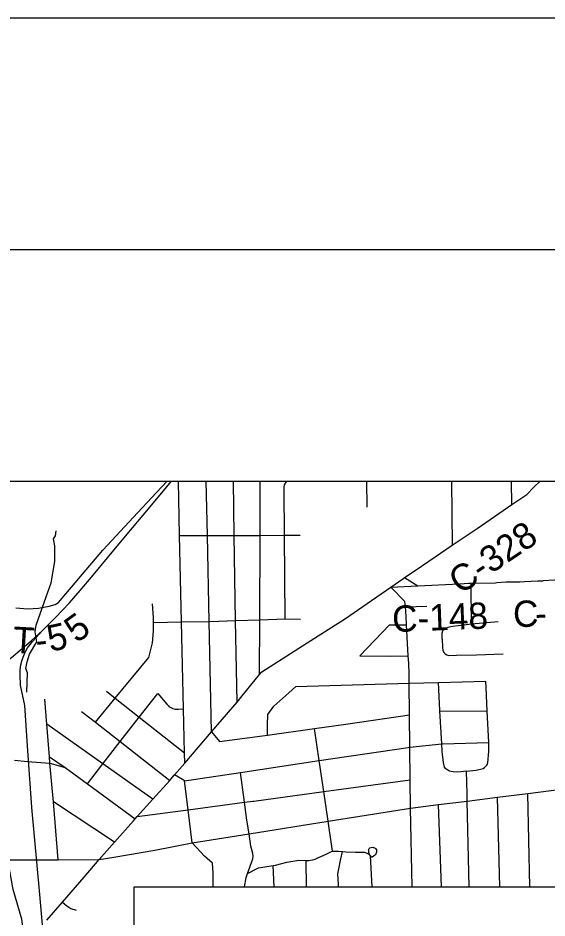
# Model space of a CAD drawing. Extents: x -37878.7 to -37844.7, y -19791.4 to -19769.4.
# Drawn here: x -37875.069 to -37873.927, y -19771.329 to -19769.385 of the extents above; entities that cross this region are included whole.
import ezdxf

# ---------------------------------------------------------------- set-up
doc = ezdxf.new("R2010")
doc.units = 0
for name, color, linetype in [('Default', 7, 'Continuous'), ('GM_X_City_Street', 7, 'Continuous'), ('GM_X_County_Road', 7, 'Continuous'), ('GM_X_County_Road_Text', 7, 'Continuous'), ('GM_X_Minor_River', 7, 'Continuous'), ('GM_X_Rail_Line', 7, 'Continuous'), ('GM_X_Township_Road', 7, 'Continuous'), ('GM_X_Township_Road_Text', 7, 'Continuous'), ('GM_X_Township_Subdivision', 7, 'Continuous'), ('SH_Border', 7, 'Continuous'), ('SH_Cut_Line', 7, 'Continuous'), ('SH_Data', 7, 'Continuous'), ('TX_P_1', 7, 'Continuous')]:
    doc.layers.add(name, color=color, linetype=linetype)

msp = doc.modelspace()

# ---------------------------------------------------------------- linework, layer by layer
at = {"layer": 'Default'}
msp.add_lwpolyline([(-37874.2328, -19770.6572), (-37874.1867, -19770.6558)], dxfattribs=at)
at = {"layer": 'GM_X_City_Street'}
for points in [[(-37874.7092, -19770.9945), (-37874.7097, -19770.9726), (-37874.7118, -19770.877), (-37874.7161, -19770.6896), (-37874.7203, -19770.5032), (-37874.7229, -19770.3854)], [(-37874.6512, -19770.9272), (-37874.6564, -19770.6884), (-37874.6603, -19770.503), (-37874.6628, -19770.3854)], [(-37874.5964, -19770.8629), (-37874.5993, -19770.6867), (-37874.6022, -19770.5028), (-37874.6041, -19770.3854)], [(-37874.5477, -19770.8032), (-37874.5473, -19770.6849), (-37874.5467, -19770.5027), (-37874.5463, -19770.3854)], [(-37874.4921, -19770.683), (-37874.4937, -19770.5025), (-37874.4946, -19770.4047), (-37874.4944, -19770.3975), (-37874.4936, -19770.3933), (-37874.4904, -19770.3875), (-37874.4891, -19770.3854)], [(-37874.3153, -19770.442), (-37874.316, -19770.3854)], [(-37874.8105, -19770.4532), (-37874.7704, -19770.4102), (-37874.7704, -19770.4102)], [(-37874.7203, -19770.5032), (-37874.6603, -19770.503), (-37874.6022, -19770.5028), (-37874.5467, -19770.5027), (-37874.4937, -19770.5025), (-37874.4603, -19770.5024)], [(-37874.1157, -19770.607), (-37874.0957, -19770.606)], [(-37874.0897, -19770.6937), (-37874.0907, -19770.6058)], [(-37874.0355, -19770.6047), (-37874.0353, -19770.6047), (-37874.0156, -19770.603), (-37874.0155, -19770.603)], [(-37874.9023, -19770.9063), (-37874.8593, -19770.8543), (-37874.7867, -19770.7665), (-37874.779, -19770.7347), (-37874.7768, -19770.7094), (-37874.7768, -19770.6909), (-37874.7768, -19770.6798), (-37874.779, -19770.6502)], [(-37874.4368, -19770.7295), (-37874.4367, -19770.7295), (-37874.362, -19770.6821), (-37874.3154, -19770.6497)], [(-37874.7768, -19770.6909), (-37874.7161, -19770.6896), (-37874.6564, -19770.6884), (-37874.636, -19770.6879), (-37874.5993, -19770.6867), (-37874.5473, -19770.6849), (-37874.4921, -19770.683), (-37874.4596, -19770.6837)], [(-37874.3311, -19770.7627), (-37874.267, -19770.6958)], [(-37874.1536, -19770.7265), (-37874.1536, -19770.7129), (-37874.1516, -19770.7086), (-37874.1502, -19770.7062), (-37874.1456, -19770.703), (-37874.14, -19770.7008), (-37874.1372, -19770.7001), (-37874.1307, -19770.6989), (-37874.1188, -19770.6972), (-37874.0897, -19770.6937), (-37874.0325, -19770.6883)], [(-37875.0071, -19771.3333), (-37874.9736, -19771.2948), (-37874.9266, -19771.2409), (-37874.8938, -19771.2024), (-37874.8608, -19771.1652), (-37874.8203, -19771.1194), (-37874.8162, -19771.1149), (-37874.812, -19771.1101), (-37874.778, -19771.0722), (-37874.7417, -19771.0318), (-37874.739, -19771.0288), (-37874.7314, -19771.02), (-37874.7092, -19770.9945), (-37874.6512, -19770.9272), (-37874.6054, -19770.874), (-37874.5964, -19770.8629), (-37874.5854, -19770.8493), (-37874.5477, -19770.8032), (-37874.5431, -19770.797), (-37874.4368, -19770.7295)], [(-37874.1536, -19770.7265), (-37874.1524, -19770.7444), (-37874.1515, -19770.7512), (-37874.149, -19770.7561), (-37874.1466, -19770.7584), (-37874.1434, -19770.7607), (-37874.1388, -19770.7618), (-37874.1225, -19770.761), (-37874.0793, -19770.7609), (-37874.0218, -19770.7588)], [(-37874.3311, -19770.7627), (-37874.2656, -19770.7637)], [(-37874.2251, -19770.7863), (-37874.2255, -19770.7784), (-37874.2255, -19770.7784)], [(-37874.2179, -19771.262), (-37874.222, -19771.0918), (-37874.2225, -19771.0309), (-37874.2232, -19770.9601), (-37874.2238, -19770.8905), (-37874.2244, -19770.822), (-37874.2246, -19770.7943)], [(-37874.5306, -19770.9339), (-37874.5307, -19770.9118), (-37874.5296, -19770.8897), (-37874.5167, -19770.8717), (-37874.4848, -19770.8424), (-37874.4694, -19770.8289), (-37874.2244, -19770.822), (-37874.161, -19770.8202), (-37874.0591, -19770.8173)], [(-37874.1006, -19771.0122), (-37874.1195, -19771.0141), (-37874.1292, -19771.0134), (-37874.1371, -19771.0117), (-37874.1409, -19771.0096), (-37874.1457, -19771.0068), (-37874.1484, -19771.003), (-37874.1502, -19770.993), (-37874.1533, -19770.9695), (-37874.1542, -19770.9529), (-37874.1582, -19770.8819), (-37874.1583, -19770.8807), (-37874.161, -19770.8202)], [(-37874.1006, -19771.0122), (-37874.0795, -19771.0099), (-37874.0648, -19771.0063), (-37874.0615, -19771.0038), (-37874.057, -19770.9986), (-37874.0553, -19770.9965), (-37874.0543, -19770.9941), (-37874.0525, -19770.9697), (-37874.0525, -19770.95), (-37874.0558, -19770.8821), (-37874.0582, -19770.831), (-37874.0591, -19770.8173)], [(-37874.9196, -19771.039), (-37874.886, -19770.9959), (-37874.8487, -19770.9481), (-37874.8074, -19770.8953), (-37874.7673, -19770.8438)], [(-37874.8782, -19770.8394), (-37874.8593, -19770.8543), (-37874.8074, -19770.8953), (-37874.7097, -19770.9726)], [(-37874.7673, -19770.8438), (-37874.7478, -19770.8673), (-37874.7446, -19770.871), (-37874.7429, -19770.8727), (-37874.7395, -19770.8746), (-37874.7349, -19770.8767), (-37874.73, -19770.8778), (-37874.7231, -19770.8782), (-37874.7118, -19770.877)], [(-37874.9824, -19771.2034), (-37874.993, -19771.0781), (-37875.0007, -19770.9949), (-37875.0011, -19770.9812), (-37875.0072, -19770.9102), (-37875.0117, -19770.8567)], [(-37874.9323, -19770.8828), (-37874.9023, -19770.9063), (-37874.8487, -19770.9481), (-37874.7417, -19771.0318)], [(-37874.6512, -19770.9272), (-37874.6344, -19770.948), (-37874.5306, -19770.9339), (-37874.4291, -19770.92), (-37874.3612, -19770.9106), (-37874.2238, -19770.8905)], [(-37874.1582, -19770.8819), (-37874.0558, -19770.8821)], [(-37874.778, -19771.0722), (-37874.886, -19770.9959), (-37875.0072, -19770.9102)], [(-37874.8938, -19771.2024), (-37874.8625, -19771.1977), (-37874.7737, -19771.1822), (-37874.6932, -19771.1668), (-37874.5704, -19771.1472), (-37874.3994, -19771.12), (-37874.222, -19771.0918), (-37874.1614, -19771.0842), (-37874.0992, -19771.0764), (-37874.0336, -19771.0681), (-37873.968, -19771.0599), (-37873.8957, -19771.0508), (-37873.5871, -19771.008), (-37873.5852, -19771.0077), (-37873.3651, -19770.974), (-37873.3072, -19770.9662), (-37873.2357, -19770.9566), (-37873.1722, -19770.948), (-37873.0796, -19770.9272)], [(-37874.3898, -19771.1846), (-37874.3994, -19771.12), (-37874.4089, -19771.056), (-37874.4189, -19770.9891), (-37874.4291, -19770.92)], [(-37874.7097, -19771.0326), (-37874.589, -19771.0146), (-37874.4189, -19770.9891), (-37874.227, -19770.9605), (-37874.2232, -19770.9601), (-37874.1542, -19770.9529), (-37874.1522, -19770.9527), (-37874.0525, -19770.95)], [(-37875.077, -19770.9878), (-37875.0487, -19770.9908), (-37875.0007, -19770.9949), (-37874.9675, -19771.0038), (-37874.9196, -19771.039), (-37874.8162, -19771.1149)], [(-37875.0011, -19770.9812), (-37874.9675, -19771.0038)], [(-37875.054, -19771.387), (-37875.0615, -19771.3316), (-37875.0796, -19771.2673), (-37875.0916, -19771.2032), (-37875.1119, -19771.1277), (-37875.1285, -19771.0632), (-37875.1397, -19770.9894)], [(-37874.714, -19771.0301), (-37874.7314, -19771.02)], [(-37874.5805, -19771.262), (-37874.5766, -19771.2412), (-37874.5735, -19771.2325), (-37874.5688, -19771.2193), (-37874.5643, -19771.2066), (-37874.5625, -19771.2011), (-37874.5612, -19771.1956), (-37874.5619, -19771.1894), (-37874.5663, -19771.1736), (-37874.5704, -19771.1472), (-37874.5749, -19771.1178), (-37874.5802, -19771.079), (-37874.589, -19771.0146)], [(-37874.0996, -19771.061), (-37874.0996, -19771.061), (-37874.1006, -19771.0122)], [(-37874.6932, -19771.1668), (-37874.702, -19771.0954), (-37874.7097, -19771.0326), (-37874.714, -19771.0301)], [(-37874.5603, -19771.0763), (-37874.4089, -19771.056), (-37874.2225, -19771.0309)], [(-37874.0952, -19771.262), (-37874.0992, -19771.0764), (-37874.0996, -19771.061)], [(-37873.9636, -19771.262), (-37873.968, -19771.0599)], [(-37874.8608, -19771.1652), (-37874.993, -19771.0781)], [(-37874.812, -19771.1101), (-37874.702, -19771.0954), (-37874.5802, -19771.079), (-37874.562, -19771.0765), (-37874.5603, -19771.0763)], [(-37874.155, -19771.262), (-37874.1614, -19771.0842)], [(-37874.029, -19771.262), (-37874.0336, -19771.0681)], [(-37874.6481, -19771.262), (-37874.6482, -19771.2312), (-37874.6494, -19771.2107), (-37874.6669, -19771.1952), (-37874.6932, -19771.1668)], [(-37874.3047, -19771.262), (-37874.3078, -19771.1945), (-37874.3104, -19771.1915), (-37874.3114, -19771.1873), (-37874.3119, -19771.1837), (-37874.3119, -19771.1806), (-37874.3113, -19771.179), (-37874.3094, -19771.1772), (-37874.3068, -19771.1765), (-37874.3033, -19771.1763), (-37874.3015, -19771.1766), (-37874.2997, -19771.1773), (-37874.2977, -19771.1785), (-37874.2964, -19771.1799), (-37874.2954, -19771.182), (-37874.295, -19771.1841), (-37874.2954, -19771.1865), (-37874.2964, -19771.1906), (-37874.2975, -19771.1923), (-37874.2995, -19771.1941), (-37874.3045, -19771.1974)], [(-37874.5735, -19771.2325), (-37874.5501, -19771.2208), (-37874.5185, -19771.2157), (-37874.5136, -19771.2149), (-37874.4888, -19771.2082), (-37874.4673, -19771.2047), (-37874.464, -19771.2044), (-37874.4472, -19771.2048), (-37874.4411, -19771.2049), (-37874.4378, -19771.2044), (-37874.4323, -19771.2032), (-37874.4276, -19771.2019), (-37874.422, -19771.1992), (-37874.4041, -19771.1909), (-37874.3911, -19771.1847), (-37874.3898, -19771.1846), (-37874.3878, -19771.1844), (-37874.3806, -19771.1844), (-37874.377, -19771.1846), (-37874.3684, -19771.1855), (-37874.361, -19771.1862), (-37874.3405, -19771.1866), (-37874.3208, -19771.187), (-37874.3195, -19771.1872), (-37874.3177, -19771.1879), (-37874.3143, -19771.1897), (-37874.3117, -19771.1913), (-37874.3078, -19771.1945), (-37874.3045, -19771.1974)], [(-37874.3769, -19771.262), (-37874.3774, -19771.2556), (-37874.3784, -19771.2335), (-37874.3764, -19771.2225), (-37874.3722, -19771.2011), (-37874.3684, -19771.1855)], [(-37875.1842, -19771.2032), (-37875.0916, -19771.2032), (-37874.9886, -19771.2035), (-37874.9824, -19771.2034), (-37874.8938, -19771.2024)], [(-37874.5163, -19771.262), (-37874.5185, -19771.2157)], [(-37874.4464, -19771.262), (-37874.4472, -19771.2048)], [(-37874.9736, -19771.2948), (-37874.9638, -19771.3029), (-37874.9556, -19771.3083), (-37874.9441, -19771.312)]]:
    msp.add_lwpolyline(points, dxfattribs=at)
at = {"layer": 'GM_X_County_Road'}
for points in [[(-37874.3154, -19770.6497), (-37874.3153, -19770.6496), (-37874.2642, -19770.6142), (-37874.2384, -19770.5967), (-37874.2343, -19770.5938), (-37874.2113, -19770.5782), (-37874.1821, -19770.5583), (-37874.1314, -19770.5238), (-37874.0778, -19770.4877), (-37874.0214, -19770.449), (-37874.0026, -19770.4362), (-37873.9707, -19770.4144), (-37873.955, -19770.3989), (-37873.9415, -19770.3854)], [(-37874.2343, -19770.5938), (-37874.2059, -19770.6114)], [(-37873.9353, -19770.6004), (-37873.8505, -19770.5952), (-37873.8453, -19770.5952), (-37873.8452, -19770.5952)], [(-37874.2642, -19770.6142), (-37874.2059, -19770.6114), (-37874.1157, -19770.607)], [(-37874.2255, -19770.7784), (-37874.2264, -19770.7626), (-37874.2302, -19770.6958), (-37874.2313, -19770.6773), (-37874.2328, -19770.6572), (-37874.2336, -19770.6458), (-37874.2642, -19770.6142)], [(-37874.0957, -19770.606), (-37874.0907, -19770.6058), (-37874.0383, -19770.605), (-37874.0355, -19770.6047)], [(-37874.0155, -19770.603), (-37873.9858, -19770.6027), (-37873.9757, -19770.6023), (-37873.9754, -19770.6023)], [(-37873.9754, -19770.6023), (-37873.9464, -19770.6011), (-37873.9354, -19770.6005), (-37873.9353, -19770.6004)], [(-37874.2246, -19770.7943), (-37874.2251, -19770.7864), (-37874.2251, -19770.7863)]]:
    msp.add_lwpolyline(points, dxfattribs=at)
at = {"layer": 'GM_X_Minor_River'}
msp.add_lwpolyline([(-37875.0502, -19770.8411), (-37875.049, -19770.7994), (-37875.0522, -19770.79), (-37875.0498, -19770.7755), (-37875.0448, -19770.7595), (-37875.0287, -19770.7326), (-37875.0321, -19770.7107), (-37875.0304, -19770.6966), (-37875.0088, -19770.6351), (-37874.998, -19770.6049), (-37874.9898, -19770.5589), (-37874.99, -19770.5255), (-37874.9929, -19770.5104), (-37874.9881, -19770.5038), (-37874.9868, -19770.4928)], dxfattribs=at)
at = {"layer": 'GM_X_Rail_Line'}
for points in [[(-37875.0167, -19770.708), (-37875.0122, -19770.7038), (-37874.9875, -19770.679), (-37874.9736, -19770.6645), (-37874.9585, -19770.6483), (-37874.9353, -19770.6217), (-37874.9072, -19770.5883), (-37874.8762, -19770.5514), (-37874.8336, -19770.5002), (-37874.7877, -19770.4455), (-37874.7377, -19770.3854)], [(-37875.0649, -19770.7931), (-37875.0632, -19770.7822), (-37875.0606, -19770.7714), (-37875.0571, -19770.7621), (-37875.0534, -19770.7537), (-37875.0486, -19770.7458), (-37875.0435, -19770.7386), (-37875.0381, -19770.732), (-37875.0167, -19770.708)], [(-37875.0645, -19770.7506), (-37875.0408, -19770.7303), (-37875.0167, -19770.708)], [(-37875.1281, -19770.8003), (-37875.1038, -19770.7824), (-37875.0834, -19770.7664), (-37875.0645, -19770.7506)], [(-37875.0001, -19771.5322), (-37875.0225, -19771.2782), (-37875.0393, -19771.09), (-37875.0489, -19770.9572), (-37875.0547, -19770.8699), (-37875.0639, -19770.8258), (-37875.065, -19770.8041), (-37875.0649, -19770.7931)]]:
    msp.add_lwpolyline(points, dxfattribs=at)
at = {"layer": 'GM_X_Township_Road'}
for points in [[(-37874.7704, -19770.4102), (-37874.7472, -19770.3854)], [(-37875.0739, -19770.6595), (-37875.0485, -19770.6611), (-37875.025, -19770.6597), (-37875.002, -19770.6556), (-37874.9895, -19770.6518), (-37874.9821, -19770.6474), (-37874.8864, -19770.5344), (-37874.8106, -19770.4533), (-37874.8105, -19770.4532)]]:
    msp.add_lwpolyline(points, dxfattribs=at)
at = {"layer": 'GM_X_Township_Subdivision'}
for points in [[(-37874.1328, -19770.3854), (-37874.1314, -19770.5238)], [(-37874.0026, -19770.4362), (-37874.0036, -19770.3854)], [(-37874.267, -19770.6958), (-37874.2302, -19770.6958)], [(-37874.2656, -19770.7637), (-37874.2264, -19770.7626)]]:
    msp.add_lwpolyline(points, dxfattribs=at)
at = {"layer": 'SH_Border'}
msp.add_lwpolyline([(-37876.6504, -19769.8854), (-37845.1504, -19769.8854), (-37845.1504, -19790.8854), (-37876.6504, -19790.8854)], close=True, dxfattribs=at)
at = {"layer": 'SH_Cut_Line'}
msp.add_lwpolyline([(-37878.6504, -19791.3854), (-37844.6504, -19791.3854), (-37844.6504, -19769.3854), (-37878.6504, -19769.3854)], close=True, dxfattribs=at)
at = {"layer": 'SH_Data'}
msp.add_line((-37876.1504, -19770.3854), (-37869.1504, -19770.3854), dxfattribs=at)
at = {"layer": 'TX_P_1'}
for p, q in [((-37874.8187, -19771.262), (-37873.0606, -19771.262)), ((-37874.8187, -19771.8611), (-37874.8187, -19771.262))]:
    msp.add_line(p, q, dxfattribs=at)

# ---------------------------------------------------------------- texts
at = {"layer": 'GM_X_County_Road_Text'}
for s, height, rotation, p in [('C-328', 0.05682, 34.0702, (-37874.114, -19770.6316)), ('C-148', 0.05682, 2.2015, (-37874.2603, -19770.7117)), ('C', 0.0568, 1.3759, (-37873.9996, -19770.7009)), ('-', 0.0568, 2.6888, (-37873.9516, -19770.6998))]:
    msp.add_text(s, height=height, rotation=rotation, dxfattribs=at).set_placement(p)
at = {"layer": 'GM_X_Township_Road_Text'}
for s, rotation, p in [('5', 36.046, (-37874.9427, -19770.7367)), ('5', 12.2551, (-37874.9998, -19770.7544)), ('T', 356.7217, (-37875.0818, -19770.7561)), ('-', 6.8718, (-37875.0286, -19770.7582))]:
    msp.add_text(s, height=0.0568, rotation=rotation, dxfattribs=at).set_placement(p)

doc.saveas('drawing.dxf')
